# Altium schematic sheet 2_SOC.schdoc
size 708 x 327 mm; Symbol: Sheet_A3_Whycan; Device: Sheet_A3; @Project Name: Yuzukilizard; REV: 1.0; Date: 2022-10-08; Draw By: YuzukiTsuru; Company: YuzukiHD
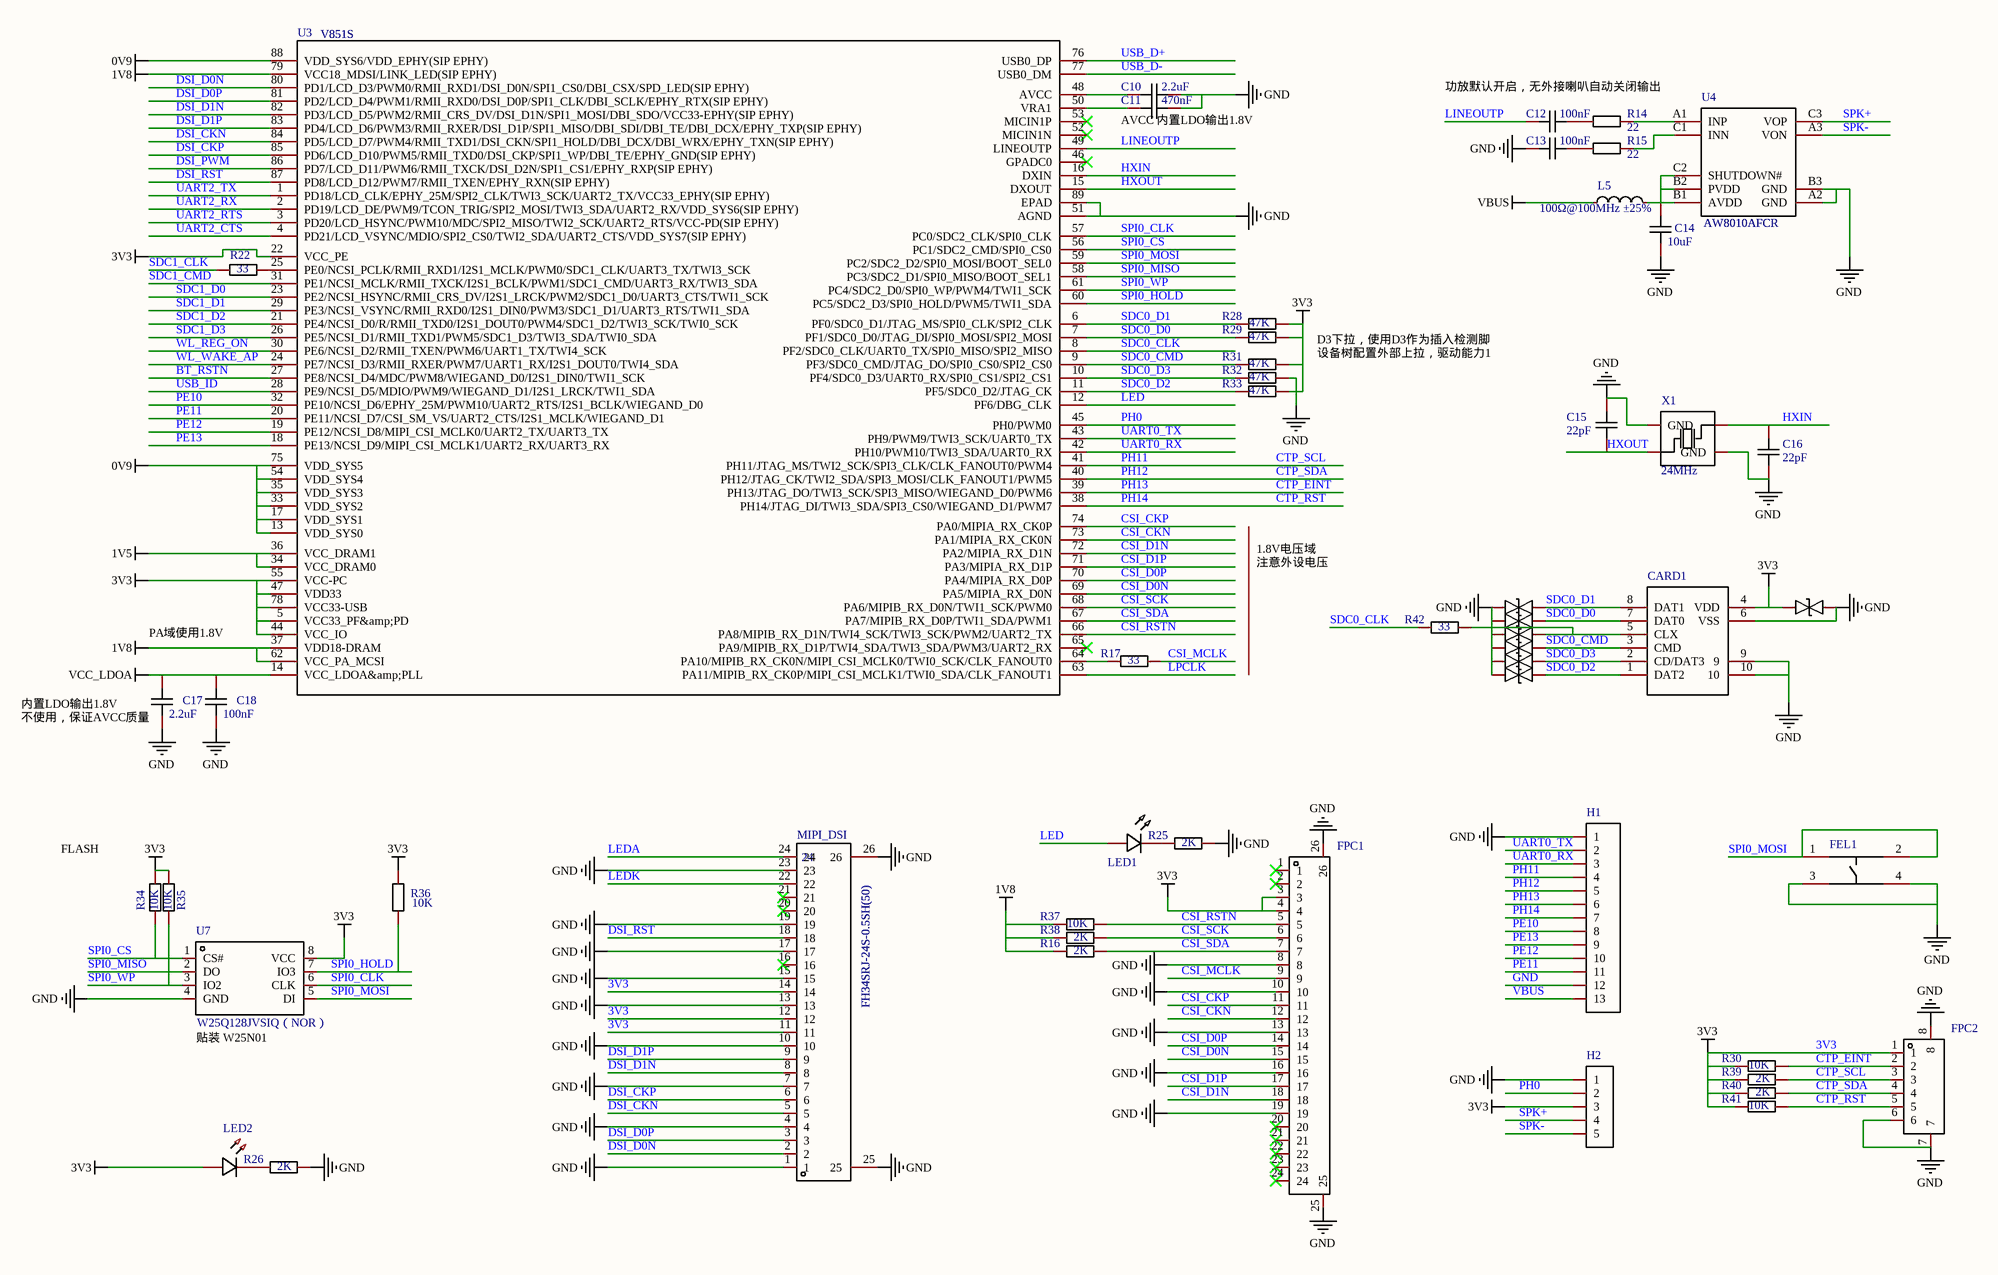
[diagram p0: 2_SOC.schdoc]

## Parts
C10  value 2.2uF  [C0402]  (hidden comment: CAP_0402)
C11  value 470nF  [C0402]  (hidden comment: CAP_0402)
C12  value 100nF  [C0402]  (hidden comment: CAP_0402)
C13  value 100nF  [C0402]  (hidden comment: CAP_0402)
C14  value 10uF  [C0603 NSK]  (hidden comment: CAP_0603)
C15  value 22pF  [C0402]  (hidden comment: CAP_0402)
C16  value 22pF  [C0402]  (hidden comment: CAP_0402)
C17  value 2.2uF  [C0402]  (hidden comment: CAP_0402)
C18  value 100nF  [C0402]  (hidden comment: CAP_0402)
CARD1  TF-021B-H265  [TF-SMD_TF-021B-H265]  (value not drawn)
D6  0402ESDA-05N  [D0402]  (value not drawn)
D8  0402ESDA-05N  [D0402]  (value not drawn)
D9  0402ESDA-05N  [D0402]  (value not drawn)
D10  0402ESDA-05N  [D0402]  (value not drawn)
D11  0402ESDA-05N  [D0402]  (value not drawn)
D12  0402ESDA-05N  [D0402]  (value not drawn)
D13  0402ESDA-05N  [D0402]  (value not drawn)
FEL1  PTS810SJM250SMTRLFS  [KEY-SMD_4P-L4.2-W3.2-P2.20-LS4.6]  (value not drawn)
FPC1  F0502-B-24-10G-R  [FPC-SMD_F0502-B-24-10G-R]  (value not drawn)
FPC2  FH19C-6S-0.5SH(10)  [FPC-SMD_FH19C-6S-0.5SH]  (value not drawn)
H1  HDR-F_2.54_1x13P  [HDR-TH_13P-P2.54-V-F]  (value not drawn)
H2  HDR-F_2.54_1x5P  [HDR-TH_5P-P2.54-V-F]  (value not drawn)
L5  LCSC Part Name: 100Ω@100MHz ±25%  [L0603]  (hidden comment: UPZ1608E101-3R0TF)
LED1  LED_0603-R  [LED0603-RD_BLUE]  (value not drawn)
LED2  LED_0807-RGB  [RGBLED_0807]  (value not drawn)
MIPI_DSI  FH34SRJ-24S-0.5SH(50)  NAME: 24  [FFC-SMD_24P-P0.50_FH34SRJ-24S-0.5SH]
R14  value 22  [R0402]  (hidden comment: Res_0402)
R15  value 22  [R0402]  (hidden comment: Res_0402)
R16  value 2K  [R0402]  (hidden comment: Res_0402)
R17  value 33  [R0402]  (hidden comment: Res_0402)
R22  value 33  [R0402]  (hidden comment: Res_0402)
R25  value 2K  [R0402]  (hidden comment: Res_0402)
R26  value 2K  [R0402]  (hidden comment: Res_0402)
R28  value 47K  [R0402]  (hidden comment: Res_0402)
R29  value 47K  [R0402]  (hidden comment: Res_0402)
R30  value 10K  [R0402]  (hidden comment: Res_0402)
R31  value 47K  [R0402]  (hidden comment: Res_0402)
R32  value 47K  [R0402]  (hidden comment: Res_0402)
R33  value 47K  [R0402]  (hidden comment: Res_0402)
R34  value 10K  [R0402]  (hidden comment: Res_0402)
R35  value 10K  [R0402]  (hidden comment: Res_0402)
R36  value 10K  [R0402]  (hidden comment: Res_0402)
R37  value 10K  [R0402]  (hidden comment: Res_0402)
R38  value 2K  [R0402]  (hidden comment: Res_0402)
R39  value 2K  [R0402]  (hidden comment: Res_0402)
R40  value 2K  [R0402]  (hidden comment: Res_0402)
R41  value 10K  [R0402]  (hidden comment: Res_0402)
R42  value 33  [R0402]  (hidden comment: Res_0402)
U3  V851S  [QFN-88_L9.0-W9.0-P0.35-BL-EP5.26]
U4  AW8010AFCR  [FC-9_L1.5-W1.5-R3-C3-P0.50-BL]
U7  Manufacturer Part: W25Q128JVSIQ（NOR）  [SOIC-8_L5.3-W5.3-P1.27-LS8.0-BL_1]  (hidden comment: W25Q128JVSIQ)
X1  value 24MHz  [OSC-SMD_4P-L2.0-W1.6-BL]  (hidden comment: Q22FA12800489)

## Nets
0V9: U3.13(VDD_SYS0) U3.17(VDD_SYS1) U3.33(VDD_SYS2) U3.35(VDD_SYS3) U3.54(VDD_SYS4) U3.75(VDD_SYS5) U3.88(VDD_SYS6/VDD_EPHY(SIP_EPHY))
1V5: U3.34(VCC_DRAM0) U3.36(VCC_DRAM1)
1V8: R16.1 R37.1 R38.1 U3.37(VDD18-DRAM) U3.62(VCC_PA_MCSI) U3.79(VCC18_MDSI/LINK_LED(SIP_EPHY))
3V3: CARD1.4(VDD) D6.2 FPC1.3 FPC1.4 FPC2.1 H2.3 LED2.1(A) MIPI_DSI.11 MIPI_DSI.12 MIPI_DSI.14 R28.2 R29.2 R30.1 R31.2 R33.2 R34.2 R35.2 R36.2 R39.1 R40.1 R41.1 U3.5(VCC33_PF&amp;PD) U3.22(VCC_PE) U3.44(VCC_IO) U3.47(VDD33) U3.55(VCC-PC) U3.78(VCC33-USB) U7.8(VCC)
GND: C10.2 C11.2 C13.1 C14.1 C15.2 C16.2 C17.1 C18.1 CARD1.6(VSS) CARD1.9 CARD1.10 D6.1 D8.2 D9.2 D10.2 D11.2 D12.2 D13.2 FEL1.3 FEL1.4 FPC1.8 FPC1.10 FPC1.13 FPC1.16 FPC1.19 FPC1.25 FPC1.26 FPC2.6 FPC2.7 FPC2.8 H1.1 H1.12 H2.1 MIPI_DSI.1 MIPI_DSI.4 MIPI_DSI.7 MIPI_DSI.10 MIPI_DSI.13 MIPI_DSI.15 MIPI_DSI.17 MIPI_DSI.19 MIPI_DSI.23 MIPI_DSI.25 MIPI_DSI.26 R25.2 R26.2 R32.2 U3.51(AGND) U3.89(EPAD) U4.A2(GND) U4.B3(GND) U7.4(GND) X1.2(GND) X1.4(GND)
VBUS: H1.13 L5.1
VCC_LDOA: C17.2 C18.2 U3.14(VCC_LDOA&amp;PLL)
BT_RSTN: U3.27(PE8/NCSI_D4/MDC/PWM8/WIEGAND_D0/I2S1_DIN0/TWI1_SCK)
CSI_CKN: FPC1.12 U3.73(PA1/MIPIA_RX_CK0N)
CSI_CKP: FPC1.11 U3.74(PA0/MIPIA_RX_CK0P)
CSI_D0N: FPC1.15 U3.69(PA5/MIPIA_RX_D0N)
CSI_D0P: FPC1.14 U3.70(PA4/MIPIA_RX_D0P)
CSI_D1N: FPC1.18 U3.72(PA2/MIPIA_RX_D1N)
CSI_D1P: FPC1.17 U3.71(PA3/MIPIA_RX_D1P)
CSI_MCLK: FPC1.9 R17.2
CSI_RSTN: FPC1.5 R37.2 U3.66(PA8/MIPIB_RX_D1N/TWI4_SCK/TWI3_SCK/PWM2/UART2_TX)
CSI_SCK: FPC1.6 R38.2 U3.68(PA6/MIPIB_RX_D0N/TWI1_SCK/PWM0)
CSI_SDA: FPC1.7 R16.2 U3.67(PA7/MIPIB_RX_D0P/TWI1_SDA/PWM1)
CTP_EINT: FPC2.2 H1.6 R30.2 U3.39(PH13/JTAG_DO/TWI3_SCK/SPI3_MISO/WIEGAND_D0/PWM6)  [also labelled PH13]
CTP_RST: FPC2.5 H1.7 R41.2 U3.38(PH14/JTAG_DI/TWI3_SDA/SPI3_CS0/WIEGAND_D1/PWM7)  [also labelled PH14]
CTP_SCL: FPC2.3 H1.4 R39.2 U3.41(PH11/JTAG_MS/TWI2_SCK/SPI3_CLK/CLK_FANOUT0/PWM4)  [also labelled PH11]
CTP_SDA: FPC2.4 H1.5 R40.2 U3.40(PH12/JTAG_CK/TWI2_SDA/SPI3_MOSI/CLK_FANOUT1/PWM5)  [also labelled PH12]
DSI_CKN: MIPI_DSI.5 U3.84(PD5/LCD_D7/PWM4/RMII_TXD1/DSI_CKN/SPI1_HOLD/DBI_DCX/DBI_WRX/EPHY_TXN(SIP_EPHY))
DSI_CKP: MIPI_DSI.6 U3.85(PD6/LCD_D10/PWM5/RMII_TXD0/DSI_CKP/SPI1_WP/DBI_TE/EPHY_GND(SIP_EPHY))
DSI_D0N: MIPI_DSI.2 U3.80(PD1/LCD_D3/PWM0/RMII_RXD1/DSI_D0N/SPI1_CS0/DBI_CSX/SPD_LED(SIP_EPHY))
DSI_D0P: MIPI_DSI.3 U3.81(PD2/LCD_D4/PWM1/RMII_RXD0/DSI_D0P/SPI1_CLK/DBI_SCLK/EPHY_RTX(SIP_EPHY))
DSI_D1N: MIPI_DSI.8 U3.82(PD3/LCD_D5/PWM2/RMII_CRS_DV/DSI_D1N/SPI1_MOSI/DBI_SDO/VCC33-EPHY(SIP_EPHY))
DSI_D1P: MIPI_DSI.9 U3.83(PD4/LCD_D6/PWM3/RMII_RXER/DSI_D1P/SPI1_MISO/DBI_SDI/DBI_TE/DBI_DCX/EPHY_TXP(SIP_EPHY))
DSI_PWM: U3.86(PD7/LCD_D11/PWM6/RMII_TXCK/DSI_D2N/SPI1_CS1/EPHY_RXP(SIP_EPHY))
DSI_RST: MIPI_DSI.18 U3.87(PD8/LCD_D12/PWM7/RMII_TXEN/EPHY_RXN(SIP_EPHY))
HXIN: C16.1 U3.16(DXIN) X1.1(OSC1)
HXOUT: C15.1 U3.15(DXOUT) X1.3(OSC2)
LED: LED1.2(A) U3.12(PF6/DBG_CLK)
LEDA: MIPI_DSI.24
LEDK: MIPI_DSI.22
LINEOUTP: C12.1 U3.49(LINEOUTP)
LPCLK: U3.63(PA11/MIPIB_RX_CK0P/MIPI_CSI_MCLK1/TWI0_SDA/CLK_FANOUT1)
PE10: H1.8 U3.32(PE10/NCSI_D6/EPHY_25M/PWM10/UART2_RTS/I2S1_BCLK/WIEGAND_D0)
PE11: H1.11 U3.20(PE11/NCSI_D7/CSI_SM_VS/UART2_CTS/I2S1_MCLK/WIEGAND_D1)
PE12: H1.10 U3.19(PE12/NCSI_D8/MIPI_CSI_MCLK0/UART2_TX/UART3_TX)
PE13: H1.9 U3.18(PE13/NCSI_D9/MIPI_CSI_MCLK1/UART2_RX/UART3_RX)
PH0: H2.2 U3.45(PH0/PWM0)
SDC0_CLK: R42.1 U3.8(PF2/SDC0_CLK/UART0_TX/SPI0_MISO/SPI2_MISO)
SDC0_CMD: CARD1.3(CMD) D11.1 R31.1 U3.9(PF3/SDC0_CMD/JTAG_DO/SPI0_CS0/SPI2_CS0)
SDC0_D0: CARD1.7(DAT0) D9.1 R29.1 U3.7(PF1/SDC0_D0/JTAG_DI/SPI0_MOSI/SPI2_MOSI)
SDC0_D1: CARD1.8(DAT1) D8.1 R28.1 U3.6(PF0/SDC0_D1/JTAG_MS/SPI0_CLK/SPI2_CLK)
SDC0_D2: CARD1.1(DAT2) D13.1 R33.1 U3.11(PF5/SDC0_D2/JTAG_CK)
SDC0_D3: CARD1.2(CD/DAT3) D12.1 R32.1 U3.10(PF4/SDC0_D3/UART0_RX/SPI0_CS1/SPI2_CS1)
SDC1_CLK: R22.1
SDC1_CMD: U3.31(PE1/NCSI_MCLK/RMII_TXCK/I2S1_BCLK/PWM1/SDC1_CMD/UART3_RX/TWI3_SDA)
SDC1_D0: U3.23(PE2/NCSI_HSYNC/RMII_CRS_DV/I2S1_LRCK/PWM2/SDC1_D0/UART3_CTS/TWI1_SCK)
SDC1_D1: U3.29(PE3/NCSI_VSYNC/RMII_RXD0/I2S1_DIN0/PWM3/SDC1_D1/UART3_RTS/TWI1_SDA)
SDC1_D2: U3.21(PE4/NCSI_D0/R/RMII_TXD0/I2S1_DOUT0/PWM4/SDC1_D2/TWI3_SCK/TWI0_SCK)
SDC1_D3: U3.26(PE5/NCSI_D1/RMII_TXD1/PWM5/SDC1_D3/TWI3_SDA/TWI0_SDA)
SPI0_CLK: U3.57(PC0/SDC2_CLK/SPI0_CLK) U7.6(CLK)
SPI0_CS: R34.1 U3.56(PC1/SDC2_CMD/SPI0_CS0) U7.1(CS#)
SPI0_HOLD: R36.1 U3.60(PC5/SDC2_D3/SPI0_HOLD/PWM5/TWI1_SDA) U7.7(IO3)
SPI0_MISO: U3.58(PC3/SDC2_D1/SPI0_MISO/BOOT_SEL1) U7.2(DO)
SPI0_MOSI: FEL1.1 FEL1.2 U3.59(PC2/SDC2_D2/SPI0_MOSI/BOOT_SEL0) U7.5(DI)
SPI0_WP: R35.1 U3.61(PC4/SDC2_D0/SPI0_WP/PWM4/TWI1_SCK) U7.3(IO2)
SPK+: H2.4 U4.C3(VOP)
SPK-: H2.5 U4.A3(VON)
UART0_RX: H1.3 U3.42(PH10/PWM10/TWI3_SDA/UART0_RX)
UART0_TX: H1.2 U3.43(PH9/PWM9/TWI3_SCK/UART0_TX)
UART2_CTS: U3.4(PD21/LCD_VSYNC/MDIO/SPI2_CS0/TWI2_SDA/UART2_CTS/VDD_SYS7(SIP_EPHY))
UART2_RTS: U3.3(PD20/LCD_HSYNC/PWM10/MDC/SPI2_MISO/TWI2_SCK/UART2_RTS/VCC-PD(SIP_EPHY))
UART2_RX: U3.2(PD19/LCD_DE/PWM9/TCON_TRIG/SPI2_MOSI/TWI3_SDA/UART2_RX/VDD_SYS6(SIP_EPHY))
UART2_TX: U3.1(PD18/LCD_CLK/EPHY_25M/SPI2_CLK/TWI3_SCK/UART2_TX/VCC33_EPHY(SIP_EPHY))
USB_D+: U3.76(USB0_DP)
USB_D-: U3.77(USB0_DM)
USB_ID: U3.28(PE9/NCSI_D5/MDIO/PWM9/WIEGAND_D1/I2S1_LRCK/TWI1_SDA)
WL_REG_ON: U3.30(PE6/NCSI_D2/RMII_TXEN/PWM6/UART1_TX/TWI4_SCK)
WL_WAKE_AP: U3.24(PE7/NCSI_D3/RMII_RXER/PWM7/UART1_RX/I2S1_DOUT0/TWI4_SDA)
NetC10_1: C10.1 U3.48(AVCC)
NetC11_1: C11.1 U3.50(VRA1)
NetC12_2: C12.2 R14.1
NetC13_2: C13.2 R15.1
NetC14_2: C14.2 L5.2 U4.B1(AVDD) U4.B2(PVDD) U4.C2(SHUTDOWN#)
NetCARD1_5: CARD1.5(CLX) D10.1 R42.2
NetLED1_1: LED1.1(C) R25.1
NetLED2_2: LED2.2(C) R26.1
NetR14_2: R14.2 U4.A1(INP)
NetR15_2: R15.2 U4.C1(INN)
NetR17_1: R17.1 U3.64(PA10/MIPIB_RX_CK0N/MIPI_CSI_MCLK0/TWI0_SCK/CLK_FANOUT0)
NetR22_2: R22.2 U3.25(PE0/NCSI_PCLK/RMII_RXD1/I2S1_MCLK/PWM0/SDC1_CLK/UART3_TX/TWI3_SCK)

Not connected (* = marked no-connect by the designer): FPC1 1* 2* 20* 21* 22* 23* 24*; MIPI_DSI 16* 20* 21*; U3 46(GPADC0)* 52(MICIN1N)* 53(MICIN1P)* 65(PA9/MIPIB_RX_D1P/TWI4_SDA/TWI3_SDA/PWM3/UART2_RX)*

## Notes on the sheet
- (near C12) 功放默认开启，无外接喇叭自动关闭输出
- (near C11) AVCC 内置LDO输出1.8V
- D3下拉，使用D3作为插入检测脚
  设备树配置外部上拉，驱动能力1
- (near R42) 1.8V电压域
  注意外设电压
- PA域使用1.8V
- (near C17) 内置LDO输出1.8V
  不使用，保证AVCC质量
- FLASH
- (near U7) 贴装 W25N01

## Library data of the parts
C10-C13 C15-C18 = CAP_0402: 容值:100nF;精度:±10%;额定电压:16V;温度系数:X7R;; Symbol: C1210X7R475K630NT; Convert to PCB: yes
C14 = CAP_0603: 容值:100nF;精度:±10%;额定电压:50V;温度系数:X7R;; Symbol: C1210X7R475K630NT; Convert to PCB: yes
CARD1 = TF-021B-H265: 卡连接方式:拔插式;卡类型:MicroSD卡(TF卡);连接器类型:卡座;本体最大高度:2.5mm;工作温度范围:-25~+75;; Manufacturer: SOFNG(硕方); Add into BOM: yes; Card Connection Mode: 拔插式; Connector Type: 卡座; Maximum Body Height: 2.5mm
D6 D8-D13 = 0402ESDA-05N: 极性:Bidirectional;反向关断电压（典型值）:5V;击穿电压（最小值）:-;箝位电压:50V;峰值脉冲电流（10/1000us）:-;; Manufacturer: BORN伯恩半导体; Add into BOM: yes; Voltage - Reverse Standoff (Typ): 5V; Voltage - Clamping (Max) @ Ipp: 50V
FEL1 = PTS810SJM250SMTRLFS: 触点电流:50mA;额定电压(DC):16V;电路结构:单刀单掷;安装方式:立贴;按钮形状:圆形按钮;带灯:-;开关长度:4.2mm;开关宽度:3.2mm;开关高度:2.5mm;; Manufacturer: C&K; Add into BOM: yes; Contact Current: 50mA; Voltage Rating (DC): 16V; Circuit: 单刀单掷; Actuator Style: 圆形按钮; Switch Length: 4.2mm; Switch Width: 3.2mm; Switch Height: 2.5mm
FPC1 = F0502-B-24-10G-R: 间距:0.5mm;触点数量:24;锁定特性:翻盖式;安装类型:卧贴;触点类型:下接;; Manufacturer: XFCN(台湾兴飞); Add into BOM: yes; Pitch: 0.5mm; Number of Contacts: 24; Locking Feature: 翻盖式; FFC, FCB Thickness: 0.3mm
FPC2 = FH19C-6S-0.5SH(10): 间距:0.5mm;触点数量:6;锁定特性:翻盖式;安装类型:卧贴;触点类型:下接;; Manufacturer: HRS(广濑); Add into BOM: yes; Pitch: 0.5mm; Number of Contacts: 6; Locking Feature: 翻盖式; FFC, FCB Thickness: 0.2mm
H1 = HDR-F_2.54_1x13P: Convert to PCB: yes
H2 = HDR-F_2.54_1x5P: Symbol: Header-Female-2.54_1x5; Convert to PCB: yes
L5 = UPZ1608E101-3R0TF: 标称阻抗@测试频率:100Ω@100MHz;误差:±25%;直流电阻(RDC):30mΩ;额定电流:3A;电路数:1;; Manufacturer: Sunlord(顺络); Add into BOM: yes; Tolerance: ±25%; DC Resistance: 30mΩ; Current Rating: 3A; Circuits: 1
LED1 = LED_0603-R: 发光颜色:红灯;二极管配置:-;透镜颜色:无色透明;主波长:617.5nm;峰值波长:632nm;色温:-;光通量(25时):-;测试电流:5mA;正向电压(VF):2.2V;发光强度:28.5mcd;功率:60mW;发光角度:120°;安装方式:-;工作温度:-40~+85;; Symbol: LED_R; Convert to PCB: yes
LED2 = LED_0807-RGB: Symbol: LED_G; Convert to PCB: yes
MIPI_DSI = FH34SRJ-24S-0.5SH(50): 间距:0.5mm;触点数量:24;锁定特性:-;安装类型:卧贴;触点类型:双侧触点/上下接;; Manufacturer: HRS(广濑); Add into BOM: yes; Pitch: 0.5mm; FFC, FCB Thickness: 0.3mm
R14-R17 R22 R25 R26 R28-R42 = Res_0402: Symbol: 电阻; Convert to PCB: yes
U3 = V851S: Symbol: V851S_QFN88; Convert to PCB: yes
U4 = AW8010AFCR: 音频功率放大器的类型:Class D;输出类型:1-Channel (Mono);输出功率:1.15W x 1 @ 8Ω;工作电压:-;; Manufacturer: AWINIC(艾为); Add into BOM: yes
U7 = W25Q128JVSIQ: 存储器构架(格式):FLASH;存储器接口类型:SPI - Dual/Quad I/O;存储器容量:128Mb (16M x 8);; Manufacturer: WINBOND(华邦); Symbol: W25Q128JVSIQTR; Add into BOM: yes; Memory Format: FLASH; Voltage - Supply: 2.7V ~ 3.6V
X1 = Q22FA12800489: 晶振类型:贴片无源晶振;频率:24MHz;频率公差:±10ppm;频率稳定度:-;负载电容:12pF;等效串联电阻(ESR):80Ω;工作温度:-40~+85;; Manufacturer: EPSON(爱普生); Add into BOM: yes; Crystal Type: 贴片无源晶振; Frequency Tolerance: ±10ppm; Load Capacitance: 12pF; Equivalent Series Resistance (ESR): 80Ω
